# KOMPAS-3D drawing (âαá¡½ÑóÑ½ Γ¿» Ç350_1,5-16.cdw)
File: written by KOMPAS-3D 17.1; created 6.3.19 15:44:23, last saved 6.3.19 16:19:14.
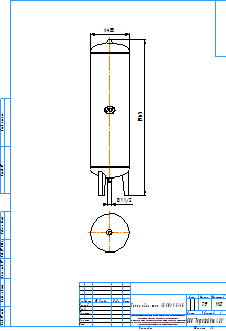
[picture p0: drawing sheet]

Sheet 1: A3, portrait

Title block, sheet 1: name: Гранлевел тип А350/1,5-16; material: Сталь 10  ГОСТ 1050-88; mass: 79; sheets: 1; sheet format: A3; stored path: C:\Users\kka\KOMPAS_Work\!Trash\ГРАНЛЕВЕЛ тип А Расширительный бак\KOMPAS 2D\Гранлевел тип А350_1,5-16.cdw

Views: Вид 1, Проекционный вид 2
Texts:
  kka
  adl
  Рама для чертежей
  Лит-Масса-Масштаб
  Материал-Предприятие
  Масштаб
  Изм.
  Лист
  № докум.
  Подп.
  Дата
  Лит.
  Разраб.
  Пров.
  Т.контр.
  Листов
  Внимание! Данный продукт является объектом авторского права ООО «Торговый Дом АДЛ».
  Запрещается изменение, копирование, распространение
  (в том числе путем копирования на другие сайты и ресурсы в Интернете)
  или любое иное использование информации и объектов без предварительного
  согласия правообладателя (ООО «Торговый Дом АДЛ»).
  Н.контр.
  Утв.
  ООО "Торговый дом АДЛ"
  Изменение
  Номер документа
  Подпись
  Обозначение документа
  Наименование изделия
  Масса изделия по ГОСТ 2.109-73
  Порядковый номер листа
  Общее количество листов в документе
  Характер работы, выполненной лицом, подписавшим документ
  Наименование или индекс предприятия, выпускающего документ
  Инв. № подл.
  Подп. и дата
  Взам. инв. №
  Инв. № дубл.
  Инвентарный номер подлинника по ГОСТ 2.501-68
  Подпись принявшего подлинник в отдел технической документации
  Инвентарный номер подлинника, взамен которого выпущен данный подлинник
  Инвентарный номер дубликата по ГОСТ 2.502-68
  Подпись принявшего дубликат в отдел технической документации
  Справ. №
  Перв. примен.
  Обозначение документа, взамен или на основании которого выпущен данный документ
  Обозначение документа, в котором впервые записан данный документ
  Подпись лица, копировавшего чертеж
  Обозначение формата листа
  !Рама для чертежа
Dimensions and other numbers on the sheet: 1965; 485; 1 1/2; 1:10; 1; 79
